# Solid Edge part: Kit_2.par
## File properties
Sűrűség: 0,000 kg/m^3
Pontosság: 0,990
Author: bmolnar
Last saved by: ahadarics
Revision: 76
Username: bmolnar
Dokumentum tartalom típus: 0
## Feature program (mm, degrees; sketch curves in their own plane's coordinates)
base feature "unnamed BaseFeature 1"
sketch for "unnamed Hole 1" plane through (44.5, 44.5, 16.5) normal (0, 0, 1) x-axis (0, -1, 0)
  hole centre (0, 0) bore radius 4.188
hole "unnamed Hole 1" through
sketch for "unnamed Hole 2" plane through (44.5, 44.5, 16.5) normal (0, 0, 1) x-axis (0, -1, 0)
  hole centre (89, 0) bore radius 4.188
hole "unnamed Hole 2" through
sketch for "unnamed Hole 3" plane through (44.5, 44.5, 16.5) normal (0, 0, 1) x-axis (0, -1, 0)
  hole centre (89, -89) bore radius 4.188
hole "unnamed Hole 3" through
sketch for "unnamed Hole 4" plane through (44.5, 44.5, 16.5) normal (0, 0, 1) x-axis (0, -1, 0)
  hole centre (0, -89) bore radius 4.188
hole "unnamed Hole 4" through
pattern "unnamed Pattern 1" of "unnamed Hole 1", "unnamed Hole 2", "unnamed Hole 3", "unnamed Hole 4"
sketch for "Furat_5" plane through (56.5649, 0, 9.75) normal (0.999962, 0, 0.008727) x-axis (0, -1, 0)
  hole centre (0.0007, 0.7496) bore radius 4.283
  dimension (linear) = 0.0007
hole "Furat_5" diameter 8.566 finite
thread "unnamed Thread 1"
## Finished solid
Body 1: solid body, 293 faces, 731 edges, 456 vertices.
  Faces by surface: plane 143, cylinder 70, swept 56, cone 15, torus 8, spline 1
  Edges by curve: line 430, circle 140, spline 120, ellipse 28, curve on surface 12, intersection 1
Bounding box of the edges (mm; curved faces can reach further): 113.300 x 113.300 x 19.500, from (-56.65, -56.65, 0) to (56.65, 56.65, 19.5).
Cylindrical faces by radius (mm): R0.2 x48, R0.2006 x2, R0.2007 x2, R4.188 x4, R4.283 x1, R6 x1, R6.35 x4, R6.55 x4, R6.75 x4
Conical faces (half-angle, radius in mm at the cone's reference point): 0.5 deg R12.25 x4, 0.5 deg R35 x2, 45 deg R4.185 x4, 45 deg R4.985 x4, 45 deg R6.25 x1
Toroidal faces (ring radius, tube radius in mm): R6.05 r0.3 x2, R6.15 r0.2 x6
Planar faces by outward normal: +x 16, +y 16, +z 18, -x 14, -y 14, -z 1, oblique 64
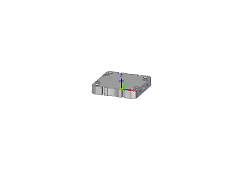
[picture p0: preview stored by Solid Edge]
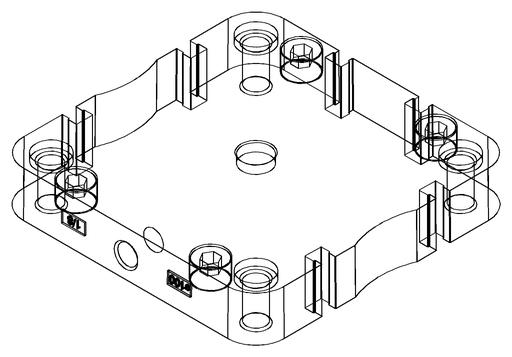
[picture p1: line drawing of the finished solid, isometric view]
